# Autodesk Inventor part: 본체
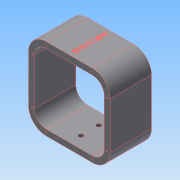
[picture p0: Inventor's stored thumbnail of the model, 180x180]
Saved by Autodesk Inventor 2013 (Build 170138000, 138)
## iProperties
Created: 2016-12
Part Number: 본체
Material: 알루미늄 6061
Document SubType Name: Modeling
Designer: mduedu
Density: 2.71 g/cm^3
Mass: 883.342 g
Surface Area: 772.714 cm^2
Volume: 325.956 cm^3
Author: mduedu
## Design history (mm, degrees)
sketch "스케치1"
  geometry: L1 (-46, 42)-(-46, -36); L2 (-16, 72)-(62, 72); L3 (92, 42)-(92, -36); L4 (62, -66)-(-16, -66); A1 r 30 centre (-16, -36) between (-46, -36) and (-16, -66); A2 r 30 centre (62, 42) between (92, 42) and (62, 72); A3 r 30 centre (62, -36) between (62, -66) and (92, -36); A4 r 30 centre (-16, 42) between (-16, 72) and (-46, 42); 1 further point
  constraints: 8 end point, 8 point on circle, 8 tangent, 4 centre point, 3 equal radius, 1 horizontal, 1 perpendicular, 1 vertical
  dimensions: "d83" = 30 radius of A2; "d84" = 92 distance from line of L3 point (0, 0); "d85" = 138 distance between parallel lines of L4 L2; "d86" = 46 distance from line of L1 point (0, 0); "d87" = 72 distance from line of point (0, 0) L2
extrude "돌출1" new body sketch "스케치1" stored distance "d3" = 70; taper "d4" = 0 deg
feature "쉘1" dims "d5" = 10
sketch "스케치10"
  geometry: L1 (78, 70)-(0, 70) reference; L2 (-30, 70)-(-30, 0) reference; 4 further points
  constraints: 1 coincident, 1 horizontal alignment, 1 midpoint, 1 vertical alignment, 1 other
  dimensions: "d88" = 35 distance of point (39, 35) point (39, 70) (derived); "d89" = 69 distance from line of point (39, 35) L2 (derived)
feature "엠보싱1" sketch "스케치10" dims "d61" = 0.5, "d62" = 0, "d83" = 30, "d84" = 92, "d85" = 138, "d86" = 46, "d87" = 72
sketch "스케치11"
  geometry: L1 (-36, -36)-(-36, 42) reference; L2 (-16, 62)-(62, 62) reference; L3 (82, 42)-(82, -36) reference; L4 (62, -56)-(-16, -56) reference; L5 (-16, -66)-(62, -66) reference; L6 (92, -36)-(92, 42) reference; L7 (62, 72)-(-16, 72) reference; L8 (-46, 42)-(-46, -36) reference; L9 (-16, 66)-(62, 66); L10 (86, 42)-(86, -36); L11 (62, -60)-(-16, -60); L12 (-40, -36)-(-40, 42); A1 r 20 centre (-16, -36) between (-36, -36) and (-16, -56) reference; A2 r 20 centre (-16, 42) between (-16, 62) and (-36, 42) reference; A3 r 20 centre (62, 42) between (82, 42) and (62, 62) reference; A4 r 20 centre (62, -36) between (62, -56) and (82, -36) reference; A5 r 30 centre (-16, -36) between (-46, -36) and (-16, -66) reference; A6 r 30 centre (62, -36) between (62, -66) and (92, -36) reference; A7 r 30 centre (62, 42) between (92, 42) and (62, 72) reference; A8 r 30 centre (-16, 42) between (-16, 72) and (-46, 42) reference; A9 r 24 centre (62, 42) between (86, 42) and (62, 66); A10 r 24 centre (62, -36) between (62, -60) and (86, -36); A11 r 24 centre (-16, -36) between (-40, -36) and (-16, -60); A12 r 24 centre (-16, 42) between (-16, 66) and (-40, 42); 8 further points
  constraints: 8 coincident, 8 end point, 8 point on circle, 4 centre point, 7 other
  dimensions: "d90" = 6 distance between parallel lines of L9 L7
hole "구멍3" sketch "스케치11" at (-16, 66), (-40, 42), (-40, -36), (-16, -60), (62, -60), (86, -36), (86, 42), (62, 66) diameter "d63" = 3.242; stored, may be unused: countersink angle "d67" = 90 deg, drill point angle "d69" = 120 deg; dims "d64" = 8.6, "d65" = 4, "d66" = 2, "d68" = 10.6
sketch "스케치12"
  geometry: L1 (16, -56)-(-62, -56) reference; L2 (-82, -36)-(-82, 42) reference; L3 (-62, 62)-(16, 62) reference; L4 (36, 42)-(36, -36) reference; L5 (46, -36)-(46, 42) reference; L6 (16, 72)-(-62, 72) reference; L7 (-92, 42)-(-92, -36) reference; L8 (-62, -66)-(16, -66) reference; L9 (-62, 66)-(16, 66); L10 (40, 42)-(40, -36); L11 (16, -60)-(-62, -60); L12 (-86, -36)-(-86, 42); A1 r 20 centre (16, -36) between (16, -56) and (36, -36) reference; A2 r 20 centre (-62, -36) between (-82, -36) and (-62, -56) reference; A3 r 20 centre (-62, 42) between (-62, 62) and (-82, 42) reference; A4 r 20 centre (16, 42) between (36, 42) and (16, 62) reference; A5 r 30 centre (16, -36) between (16, -66) and (46, -36) reference; A6 r 30 centre (16, 42) between (46, 42) and (16, 72) reference; A7 r 30 centre (-62, 42) between (-62, 72) and (-92, 42) reference; A8 r 30 centre (-62, -36) between (-92, -36) and (-62, -66) reference; A9 r 24 centre (16, 42) between (40, 42) and (16, 66); A10 r 24 centre (16, -36) between (16, -60) and (40, -36); A11 r 24 centre (-62, -36) between (-86, -36) and (-62, -60); A12 r 24 centre (-62, 42) between (-62, 66) and (-86, 42); 8 further points
  constraints: 8 coincident, 8 end point, 8 point on circle, 4 centre point, 7 other
  dimensions: "d91" = 6 distance between parallel lines of L9 L6
hole "구멍5" sketch "스케치12" at (-62, 66), (-86, 42), (-86, -36), (-62, -60), (16, -60), (40, -36), (40, 42), (16, 66) diameter "d70" = 3.242; stored, may be unused: countersink angle "d74" = 90 deg, drill point angle "d76" = 120 deg; dims "d71" = 8.6, "d72" = 4, "d73" = 2, "d75" = 10.6
sketch "스케치15"
  geometry: L1 (135.6, -35)-(-57.6, -35) reference; L2 (78, 0)-(0, 0) reference; L3 (0, -70)-(78, -70) reference; L4 (39, 0)-(39, -70); C1 r 4 at (39, -20); C2 r 4 at (39, -50); 1 further point
  constraints: 2 centre point, 2 end point, 2 midpoint, 1 point on line, 1 symmetric about line, 1 other
  dimensions: "d92" = 8 diameter of C1; "d93" = 15 distance from line of C1.centre L1
extrude "돌출6" cut sketch "스케치15" stored distance "d94" = 10; taper "d95" = 0 deg
node "솔리드1"
node "투영된 루프3"
node "투영된 루프4"
